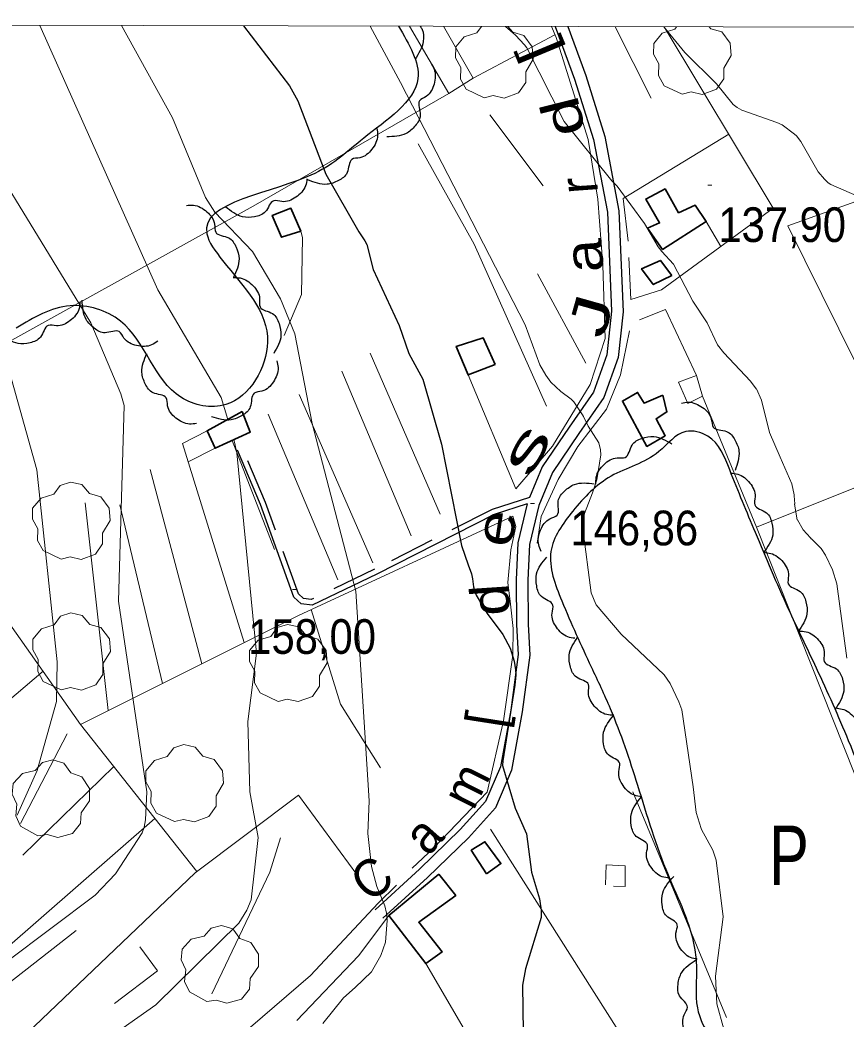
# Model space of a CAD drawing. Extents: x 480269 to 484877, y 4383588 to 4386804.
# Drawn here: x 481094.5 to 481302.9, y 4386204.5 to 4386456.6 of the extents above; entities that cross this region are included whole.
import ezdxf
from ezdxf.enums import TextEntityAlignment as Align

# ---------------------------------------------------------------- set-up
doc = ezdxf.new("R2010")
doc.units = 0
doc.header["$LTSCALE"] = 3.8
doc.linetypes.add('MEDIUM_DASHED', pattern=[4.5, 3, -1.5])
for name, color, linetype, lineweight in [('1', 7, 'Continuous', 13), ('27', 7, 'Continuous', 25), ('29', 7, 'Continuous', 13), ('38', 7, 'Continuous', 25), ('47', 7, 'Continuous', 35), ('51', 7, 'Continuous', 13), ('7', 7, 'Continuous', 13), ('8', 7, 'Continuous', 25), ('9', 7, 'Continuous', 13)]:
    doc.layers.add(name, color=color, linetype=linetype, lineweight=lineweight)
doc.layers.add('31', color=7, linetype='Continuous')
doc.layers.add('5', color=7, linetype='Continuous')

msp = doc.modelspace()

# ---------------------------------------------------------------- linework, layer by layer
at = {"layer": '1'}
msp.add_lwpolyline([(480529.1, 4386456.6), (484105.5, 4386448.1), (484100.5, 4384135.8), (480523.1, 4384144.4)], close=True, dxfattribs=at)
at = {"layer": '27'}
for points in [[(481189.94, 4386455.03), (481194.87, 4386441.86), (481181.19, 4386426.77), (481168.84, 4386417.89), (481141.6, 4386402.68), (481145.59, 4386395.9), (481156.94, 4386375.34), (481146.42, 4386359.57), (481135.09, 4386361.4), (481119.82, 4386380.64), (481107.1, 4386384.49), (481093.54, 4386378.88)], [(481195.45, 4386455.02), (481195.92, 4386454.22), (481196.23, 4386451.21), (481194.14, 4386446.72)], [(481198.09, 4386445.79), (481198.95, 4386444.23), (481198.95, 4386440.44), (481196.97, 4386437.32), (481195.27, 4386436.17), (481195.45, 4386432.62), (481194.19, 4386429.91), (481191.89, 4386427.95), (481187, 4386427.14)], [(481184.5, 4386429.24), (481184.69, 4386427.48), (481183.24, 4386423.97), (481180.22, 4386421.85), (481178.21, 4386421.43), (481177.01, 4386418.08), (481174.81, 4386416.07), (481171.94, 4386415.14), (481167.1, 4386416.26)], [(481166.88, 4386416.51), (481166.52, 4386414.77), (481164.07, 4386411.88), (481160.54, 4386410.78), (481158.5, 4386411), (481156.34, 4386408.18), (481153.63, 4386406.93), (481150.6, 4386406.93), (481146.35, 4386409.48)], [(481136.45, 4386409.79), (481138.23, 4386409.88), (481141.64, 4386408.21), (481143.56, 4386405.06), (481143.85, 4386403.03), (481147.12, 4386401.63), (481148.99, 4386399.3), (481149.74, 4386396.37), (481148.32, 4386391.62)], [(481148.27, 4386391.59), (481150.05, 4386391.51), (481153.29, 4386389.55), (481154.93, 4386386.24), (481155.04, 4386384.19), (481158.17, 4386382.51), (481159.83, 4386380.03), (481160.32, 4386377.04), (481158.48, 4386372.44)], [(481109.63, 4386385.54), (481109.38, 4386383.78), (481107.11, 4386380.74), (481103.66, 4386379.43), (481101.61, 4386379.52), (481099.63, 4386376.57), (481097, 4386375.16), (481093.98, 4386374.97), (481089.57, 4386377.25)], [(481129.21, 4386375.53), (481127.69, 4386374.61), (481123.9, 4386374.47), (481120.71, 4386376.33), (481119.49, 4386377.98), (481115.95, 4386377.67), (481113.2, 4386378.82), (481111.16, 4386381.05), (481110.16, 4386385.91)], [(481139.02, 4386354.79), (481137.25, 4386354.64), (481133.78, 4386356.17), (481131.73, 4386359.25), (481131.37, 4386361.27), (481128.05, 4386362.54), (481126.08, 4386364.79), (481125.23, 4386367.69), (481126.47, 4386372.49)], [(481159.28, 4386370.63), (481159.59, 4386368.88), (481158.39, 4386365.28), (481155.52, 4386362.96), (481153.54, 4386362.41), (481152.58, 4386358.98), (481150.52, 4386356.82), (481147.72, 4386355.7), (481142.82, 4386356.49)], [(481261.37, 4386359.92), (481263.12, 4386360.17), (481266.67, 4386358.83), (481268.89, 4386355.87), (481269.37, 4386353.88), (481272.75, 4386352.79), (481274.84, 4386350.66), (481275.86, 4386347.81), (481274.89, 4386342.95)], [(481320.35, 4386227.93), (481327.1, 4386209.36), (481329.69, 4386201.13), (481328.04, 4386199.61), (481317.88, 4386196.87), (481303.46, 4386193.44), (481292.76, 4386192), (481276.23, 4386194.04), (481268.74, 4386200.02), (481265.37, 4386207.33), (481265.15, 4386217.97), (481261.89, 4386231.76), (481257.97, 4386240.94), (481250.26, 4386263.55), (481243.38, 4386282.87), (481238.59, 4386293.38), (481231.16, 4386310.07), (481228.43, 4386322.5), (481233.94, 4386332.68), (481243.59, 4386341.49), (481255.64, 4386347.7), (481262.44, 4386352.76), (481268, 4386351.6), (481273.52, 4386343.13), (481280.01, 4386327.28), (481288.32, 4386308.12), (481295.44, 4386293.02), (481303.54, 4386274.74), (481320.35, 4386227.93)], [(481239.78, 4386339.47), (481239.86, 4386341.24), (481241.83, 4386344.48), (481245.14, 4386346.12), (481247.19, 4386346.22), (481248.88, 4386349.35), (481251.36, 4386351.01), (481254.35, 4386351.48), (481258.95, 4386349.64)], [(481273.82, 4386342.28), (481275.58, 4386342.03), (481278.62, 4386339.75), (481279.92, 4386336.3), (481279.83, 4386334.25), (481282.78, 4386332.27), (481284.19, 4386329.63), (481284.37, 4386326.62), (481282.09, 4386322.21)], [(481226, 4386322.51), (481225.35, 4386324.16), (481225.82, 4386327.92), (481228.18, 4386330.76), (481230.01, 4386331.69), (481230.28, 4386335.24), (481231.87, 4386337.76), (481234.4, 4386339.42), (481239.36, 4386339.61)], [(481234.44, 4386300.59), (481232.7, 4386300.94), (481229.8, 4386303.39), (481228.7, 4386306.91), (481228.91, 4386308.96), (481226.08, 4386311.11), (481224.83, 4386313.82), (481224.82, 4386316.84), (481227.35, 4386321.1)], [(481282.13, 4386322.23), (481283.89, 4386322.02), (481286.98, 4386319.81), (481288.36, 4386316.39), (481288.31, 4386314.34), (481291.3, 4386312.42), (481292.77, 4386309.82), (481293.02, 4386306.81), (481290.84, 4386302.35)], [(481244.27, 4386281.18), (481242.5, 4386281.35), (481239.37, 4386283.49), (481237.91, 4386286.88), (481237.91, 4386288.93), (481234.88, 4386290.78), (481233.35, 4386293.35), (481233.04, 4386296.36), (481235.12, 4386300.86)], [(481291.02, 4386302.43), (481292.78, 4386302.27), (481295.93, 4386300.15), (481297.4, 4386296.76), (481297.4, 4386294.71), (481300.44, 4386292.86), (481301.98, 4386290.3), (481302.3, 4386287.3), (481300.24, 4386282.79)], [(481300.6, 4386282.93), (481302.34, 4386282.6), (481305.27, 4386280.19), (481306.41, 4386276.68), (481306.22, 4386274.63), (481309.08, 4386272.51), (481310.37, 4386269.82), (481310.41, 4386266.8), (481307.92, 4386262.5)], [(481251.26, 4386260.62), (481249.52, 4386260.98), (481246.63, 4386263.44), (481245.55, 4386266.97), (481245.78, 4386269.01), (481242.96, 4386271.18), (481241.72, 4386273.9), (481241.73, 4386276.92), (481244.29, 4386281.17)], [(481258.26, 4386240.08), (481256.52, 4386240.44), (481253.64, 4386242.9), (481252.55, 4386246.43), (481252.77, 4386248.47), (481249.95, 4386250.63), (481248.71, 4386253.35), (481248.72, 4386256.37), (481251.27, 4386260.62)], [(481265.36, 4386219.62), (481263.64, 4386220.06), (481260.88, 4386222.67), (481259.97, 4386226.24), (481260.3, 4386228.27), (481257.59, 4386230.58), (481256.48, 4386233.35), (481256.64, 4386236.37), (481259.4, 4386240.49)], [(481265.56, 4386197.83), (481264.01, 4386198.7), (481262.01, 4386201.92), (481262.04, 4386205.61), (481262.88, 4386207.49), (481260.85, 4386210.41), (481260.49, 4386213.38), (481261.41, 4386216.25), (481265.14, 4386219.53)]]:
    msp.add_spline(points, degree=3, dxfattribs=at)
at = {"layer": '29'}
for points in [[(481211.58, 4386436.99), (481207.04, 4386439.11), (481205.63, 4386441.65), (481205.73, 4386444.63), (481204.36, 4386447.04), (481204.4, 4386449.79), (481206.56, 4386452.39), (481209.75, 4386453.39), (481210.95, 4386454.98)], [(481217.51, 4386454.96), (481218.78, 4386453.49), (481221.59, 4386452.67), (481223.72, 4386449.82), (481223.96, 4386446.69), (481222.08, 4386443.54), (481222.08, 4386440.86), (481220.26, 4386438.25), (481216.64, 4386436.91), (481213.87, 4386437.54), (481211.58, 4386436.99)], [(481261.54, 4386437.9), (481257, 4386440.02), (481255.59, 4386442.56), (481255.69, 4386445.54), (481254.32, 4386447.95), (481254.36, 4386450.7), (481256.52, 4386453.3), (481259.71, 4386454.3), (481260.13, 4386454.86)], [(481268.36, 4386454.84), (481268.74, 4386454.4), (481271.55, 4386453.58), (481273.68, 4386450.73), (481273.92, 4386447.6), (481272.04, 4386444.45), (481272.04, 4386441.77), (481270.22, 4386439.16), (481266.6, 4386437.82), (481263.83, 4386438.45), (481261.54, 4386437.9)]]:
    msp.add_lwpolyline(points, dxfattribs=at)
for points in [[(481104.82, 4386320.59), (481100.28, 4386322.71), (481098.87, 4386325.25), (481098.97, 4386328.23), (481097.6, 4386330.64), (481097.64, 4386333.39), (481099.8, 4386335.99), (481102.99, 4386336.99), (481104.64, 4386339.18), (481107.21, 4386340.01), (481110.07, 4386339.36), (481112.02, 4386337.09), (481114.83, 4386336.27), (481116.96, 4386333.42), (481117.2, 4386330.29), (481115.32, 4386327.14), (481115.32, 4386324.46), (481113.5, 4386321.85), (481109.88, 4386320.51), (481107.11, 4386321.14)], [(481104.9, 4386287.6), (481100.36, 4386289.72), (481098.95, 4386292.26), (481099.05, 4386295.24), (481097.68, 4386297.65), (481097.72, 4386300.4), (481099.88, 4386303), (481103.07, 4386304), (481104.72, 4386306.19), (481107.29, 4386307.02), (481110.15, 4386306.37), (481112.1, 4386304.1), (481114.91, 4386303.28), (481117.04, 4386300.43), (481117.28, 4386297.3), (481115.4, 4386294.15), (481115.4, 4386291.47), (481113.58, 4386288.86), (481109.96, 4386287.52), (481107.19, 4386288.15)], [(481159.57, 4386284.69), (481155.03, 4386286.81), (481153.62, 4386289.35), (481153.72, 4386292.33), (481152.35, 4386294.74), (481152.39, 4386297.49), (481154.55, 4386300.09), (481157.74, 4386301.09), (481159.39, 4386303.28), (481161.96, 4386304.11), (481164.82, 4386303.46), (481166.77, 4386301.19), (481169.58, 4386300.37), (481171.71, 4386297.52), (481171.95, 4386294.39), (481170.07, 4386291.24), (481170.07, 4386288.56), (481168.25, 4386285.95), (481164.63, 4386284.61), (481161.86, 4386285.24)], [(481133.44, 4386254.34), (481128.9, 4386256.46), (481127.49, 4386259), (481127.59, 4386261.98), (481126.22, 4386264.39), (481126.26, 4386267.14), (481128.42, 4386269.74), (481131.61, 4386270.74), (481133.26, 4386272.93), (481135.83, 4386273.76), (481138.69, 4386273.11), (481140.64, 4386270.84), (481143.45, 4386270.02), (481145.58, 4386267.17), (481145.82, 4386264.04), (481143.94, 4386260.89), (481143.94, 4386258.21), (481142.12, 4386255.6), (481138.5, 4386254.26), (481135.73, 4386254.89)], [(481099.01, 4386250.73), (481094.62, 4386253.16), (481093.4, 4386255.8), (481093.7, 4386258.76), (481092.5, 4386261.26), (481092.74, 4386264), (481095.07, 4386266.45), (481098.32, 4386267.22), (481100.12, 4386269.29), (481102.74, 4386269.94), (481105.55, 4386269.09), (481107.34, 4386266.69), (481110.09, 4386265.68), (481112.01, 4386262.69), (481112.03, 4386259.55), (481109.94, 4386256.53), (481109.75, 4386253.86), (481107.75, 4386251.38), (481104.05, 4386250.3), (481101.33, 4386251.12)], [(481141.62, 4386208.93), (481137.23, 4386211.36), (481136.01, 4386214), (481136.31, 4386216.96), (481135.11, 4386219.46), (481135.35, 4386222.2), (481137.68, 4386224.65), (481140.93, 4386225.42), (481142.73, 4386227.49), (481145.35, 4386228.14), (481148.16, 4386227.29), (481149.95, 4386224.89), (481152.7, 4386223.88), (481154.62, 4386220.89), (481154.64, 4386217.75), (481152.55, 4386214.73), (481152.36, 4386212.06), (481150.36, 4386209.58), (481146.66, 4386208.5), (481143.94, 4386209.32)]]:
    msp.add_lwpolyline(points, close=True, dxfattribs=at)
at = {"layer": '38'}
for points in [[(481232.66, 4386454.93), (481237.2, 4386442.58), (481242.06, 4386427.17), (481245.59, 4386408.46), (481246.68, 4386383), (481245.38, 4386371.44), (481241.77, 4386361.34), (481235.48, 4386352.24), (481228.8, 4386342.44), (481225.34, 4386334.13), (481223.02, 4386324.24), (481222.63, 4386315.26), (481222.66, 4386304.13), (481223.12, 4386296.37), (481221.18, 4386282.02), (481218.51, 4386267.33), (481214.44, 4386257.85), (481207.64, 4386250.28), (481197.31, 4386240.23), (481186.05, 4386229.95)], [(481229.52, 4386454.94), (481234.41, 4386441.63), (481239.19, 4386426.45), (481242.66, 4386408.13), (481243.73, 4386383.1), (481242.49, 4386372.11), (481239.13, 4386362.69), (481233.06, 4386353.9), (481226.2, 4386343.85), (481222.99, 4386336.15)], [(481222.41, 4386334.51), (481214.12, 4386331.83), (481184.54, 4386316.76), (481168.18, 4386308.96), (481165.41, 4386309.31), (481163.57, 4386310.99), (481155.12, 4386334.39), (481149.37, 4386348.03)], [(481222.41, 4386334.51), (481220.09, 4386324.65), (481219.68, 4386315.32), (481219.71, 4386304.03), (481220.17, 4386296.48), (481218.27, 4386282.48), (481215.68, 4386268.19), (481211.92, 4386259.45), (481205.51, 4386252.33), (481195.29, 4386242.38), (481184.06, 4386232.12)]]:
    msp.add_lwpolyline(points, dxfattribs=at)
at = {"layer": '38', "linetype": 'MEDIUM_DASHED'}
msp.add_lwpolyline([(481222.99, 4386336.15), (481213.59, 4386333.11), (481183.93, 4386318), (481167.95, 4386310.38), (481166.02, 4386310.63), (481164.75, 4386311.78), (481156.41, 4386334.9), (481150.65, 4386348.56)], dxfattribs=at)
at = {"layer": '47'}
for points in [[(481267.57, 4386405.76), (481264.81, 4386409.9), (481260.63, 4386407.95), (481257.22, 4386413.98), (481252.35, 4386411.43), (481255.82, 4386405.38), (481252.78, 4386404.05), (481256.59, 4386398.66)], [(481165.29, 4386403.33), (481160.46, 4386401.8), (481158.13, 4386407.27), (481162.82, 4386409.1)], [(481258.9, 4386392.13), (481256.06, 4386395.92), (481251.31, 4386393.83), (481254.22, 4386389.84)], [(481214.38, 4386369.69), (481211.3, 4386376.41), (481204.53, 4386374.24), (481207.51, 4386367.03)], [(481256.62, 4386361.96), (481251.91, 4386359.93), (481250.3, 4386362.64), (481246.45, 4386360.44), (481252.64, 4386349.02), (481257.27, 4386351.7), (481254.97, 4386355.97), (481257.7, 4386357.71)], [(481150.54, 4386357.85), (481152.58, 4386352.62), (481143.71, 4386348.56), (481141.67, 4386352.98)], [(481212.13, 4386241.2), (481215.8, 4386243.77), (481211.79, 4386249.26), (481208.33, 4386247.11)], [(481200.16, 4386241.1), (481204.4, 4386235.73), (481195.07, 4386228.97), (481200.98, 4386221.47), (481196.86, 4386218.52), (481187.53, 4386230.7)]]:
    msp.add_lwpolyline(points, close=True, dxfattribs=at)
at = {"layer": '47', "lineweight": 13}
msp.add_lwpolyline([(481265.12, 4386366.93), (481260.6, 4386365.19), (481262.99, 4386359.84), (481266.64, 4386361.71)], close=True, dxfattribs=at)
at = {"layer": '51'}
for p, q in [((481202.65, 4386438.02), (481192.74, 4386455.02)), ((481253.73, 4386436.89), (481244.59, 4386454.9)), ((481208.8, 4386441.88), (481202.65, 4386438.02)), ((481213.03, 4386432.68), (481226.48, 4386414.76)), ((481271.29, 4386399.47), (481267.57, 4386405.76)), ((481225.02, 4386392.53), (481237.25, 4386369.98)), ((481200.5, 4386331.93), (481182.85, 4386372.53)), ((481175.65, 4386368.02), (481193.13, 4386326.49)), ((481183.53, 4386319.66), (481164.94, 4386362.13)), ((481157.08, 4386357.17), (481174.65, 4386315.38)), ((481143.71, 4386348.56), (481136.93, 4386345.1)), ((481147.98, 4386350.52), (481158.66, 4386323.04)), ((481127.3, 4386343.19), (481140.35, 4386294.18)), ((481110.94, 4386334.75), (481116.75, 4386282.36)), ((481130.45, 4386289.22), (481119.63, 4386334.29)), ((481139.11, 4386241.77), (481109.74, 4386278.85)), ((481106.39, 4386276.53), (481094.56, 4386253.86)), ((481095.2, 4386245.88), (481118.14, 4386268.26)), ((481272.75, 4386204.93), (481249.08, 4386261.89)), ((481128.51, 4386255.16), (481090.48, 4386221.87)), ((481108.66, 4386226.86), (481081.61, 4386205.79)), ((481212.47, 4386191.97), (481196.86, 4386218.52))]:
    msp.add_line(p, q, dxfattribs=at)
for points in [[(481201.36, 4386455), (481208.8, 4386441.88), (481229.45, 4386452.83)], [(481207.51, 4386367.03), (481219.55, 4386338.28), (481228.85, 4386349.11), (481238.29, 4386364.66), (481242.12, 4386376.26), (481241.48, 4386394.74), (481240.25, 4386411.37), (481237.85, 4386426.45), (481229.72, 4386452.15), (481228.57, 4386454.94)], [(481248.11, 4386396.7), (481248.61, 4386386.07), (481256.32, 4386388.51), (481284.52, 4386409.15), (481257.01, 4386454.87)], [(481426.51, 4386454.47), (481382.4, 4386438.35), (481288.18, 4386404.68), (481318.33, 4386343.83), (481280.3, 4386328.64), (481266.64, 4386361.71)], [(481053.37, 4386354.18), (481153.3, 4386409.6), (481202.65, 4386438.02)], [(481273.3, 4386427.81), (481246.61, 4386411.54), (481247.93, 4386400.79)], [(481227.27, 4386359.13), (481209.04, 4386400.04), (481194.9, 4386425.38)], [(481161.09, 4386377.02), (481165.5, 4386387.37), (481165.74, 4386401.68), (481165.29, 4386403.33)], [(481265.12, 4386366.93), (481257.31, 4386383.52), (481250.74, 4386380.93)], [(481248.23, 4386378.14), (481245.97, 4386367.1), (481242.42, 4386358.39), (481235.24, 4386349), (481230.27, 4386340.64), (481225.99, 4386331.36), (481224.98, 4386324.62)], [(481151.01, 4386299.51), (481135.48, 4386349.77), (481141.67, 4386352.98)], [(481080.84, 4386319.8), (481109.74, 4386278.85), (481164.74, 4386306.39), (481218.85, 4386331.4), (481219.55, 4386328.77), (481218.29, 4386322.88), (481217.56, 4386314.64), (481218.25, 4386309.25), (481218.87, 4386303.11), (481218.83, 4386296.33), (481216.44, 4386279.79), (481212.31, 4386261.77), (481198.85, 4386247.77), (481193.39, 4386242.61)], [(481280.3, 4386328.64), (481316.03, 4386238.76), (481353.68, 4386144.85), (481396.75, 4386152.18), (481450.8, 4386166.74), (481535.15, 4386190.59)], [(481185.42, 4386267.94), (481175.34, 4386284.02), (481167.92, 4386307.86)], [(481054.37, 4386247.6), (481073.02, 4386269.07), (481100.28, 4386292.27)], [(481189.43, 4386238.35), (481184.8, 4386233.8), (481167.77, 4386215.52), (481149.6, 4386199.89), (481132.43, 4386187.68), (481111.54, 4386176.08), (481088.62, 4386168.47), (481055.25, 4386162.19), (481090.79, 4386195.75), (481138.64, 4386241.42), (481164.71, 4386260.99), (481179.45, 4386241.02)], [(481213.22, 4386252.41), (481265.46, 4386170.05), (481265.32, 4386167.49), (481264.01, 4386164.98), (481240.52, 4386149.28)], [(481142.87, 4386210.92), (481157.54, 4386241.61), (481160.2, 4386250.26)], [(481242.22, 4386238.42), (481242.32, 4386243.4), (481247.13, 4386243.18), (481247.12, 4386237.97), (481244.23, 4386238.06)], [(481187.53, 4386230.7), (481179.87, 4386220.51), (481164.3, 4386204.15)], [(481124.67, 4386222.74), (481129.13, 4386216.69), (481118.3, 4386208.48)]]:
    msp.add_lwpolyline(points, dxfattribs=at)
at = {"layer": '7'}
for p, q in [((481268, 4386414.95), (481269, 4386414.95)), ((481223.25, 4386334.64), (481224.25, 4386334.64)), ((481163.19, 4386312.88), (481164.19, 4386312.88))]:
    msp.add_line(p, q, dxfattribs=at)
at = {"layer": '8'}
msp.add_lwpolyline([(481150.83, 4386455.12), (481162.43, 4386439.95), (481164.53, 4386436.23), (481171.62, 4386417.69), (481179.93, 4386403.13), (481181.48, 4386400.89), (481181.98, 4386399.95), (481183.59, 4386393.62), (481190.15, 4386379.52), (481192.57, 4386372.47), (481196.14, 4386365.95), (481200.81, 4386349.6), (481205.9, 4386324), (481207.52, 4386319.12), (481208.38, 4386316.88), (481208.67, 4386315.61), (481208.91, 4386313.6), (481209.12, 4386312.65), (481209.54, 4386311.46), (481212.34, 4386306.82), (481216.3, 4386301.54), (481218.13, 4386298.08), (481219.14, 4386294.82), (481219.49, 4386292.66), (481219.55, 4386291.29), (481219.33, 4386288.8), (481216.26, 4386269.69), (481216.21, 4386268.51), (481219.43, 4386257.73), (481222.23, 4386251.23), (481223.5, 4386241.62), (481225.54, 4386234.85), (481225.98, 4386231.97), (481225.97, 4386230.19), (481221.97, 4386217.19), (481221.27, 4386213.07), (481221.54, 4386195.32)], dxfattribs=at)
at = {"layer": '9'}
for points in [[(481025.25, 4386167.22), (481026.34, 4386167.59), (481030.34, 4386169.8), (481062.15, 4386200.1), (481091.1, 4386219.01), (481113.42, 4386235.76), (481118.59, 4386241.2), (481125.31, 4386251.51), (481125.84, 4386252.95), (481126.17, 4386254.79), (481126.47, 4386261.82), (481119.29, 4386309.93), (481120.76, 4386359.37), (481119.92, 4386362.24), (481112.34, 4386380.2), (481073.31, 4386443.98), (481068.88, 4386455.32)], [(481146.88, 4386355.84), (481145.19, 4386361.35), (481129.27, 4386388.55), (481099.44, 4386455.24)], [(481170.84, 4386203.4), (481176.07, 4386209.91), (481179.04, 4386212.48), (481183.12, 4386216.42), (481185.51, 4386220.53), (481186.7, 4386223.96), (481187.08, 4386229.42), (481186.93, 4386231.26), (481186.5, 4386233.1), (481184.5, 4386238.01), (481183.13, 4386243.02), (481182.21, 4386251.32), (481182.58, 4386259.63), (481179.23, 4386312.48), (481168.15, 4386354.81), (481163.84, 4386377.42), (481160.2, 4386386.24), (481153.12, 4386398.21), (481143.63, 4386408.08), (481141.27, 4386411.77), (481132.97, 4386431.89), (481120.12, 4386455.2)], [(481272.08, 4386201.94), (481270.32, 4386208.4), (481269.91, 4386215.32), (481271.85, 4386230.35), (481270.14, 4386244.58), (481269.27, 4386247.1), (481266.43, 4386252.36), (481266.33, 4386252.57), (481265.06, 4386256.61), (481264.31, 4386263.11), (481261.45, 4386282.53), (481260.7, 4386284.58), (481258.49, 4386289.23), (481256.96, 4386291.38), (481256.89, 4386291.46), (481246.16, 4386301.67), (481239.85, 4386309), (481239.75, 4386309.19), (481238.58, 4386312.08), (481236.44, 4386328.21), (481236.61, 4386330.92), (481236.88, 4386332.07), (481238.95, 4386337.32), (481240.04, 4386340.61), (481241.05, 4386346.9), (481240.96, 4386348.13), (481240.52, 4386349.94), (481237.79, 4386354.14), (481236.63, 4386356.59), (481236.43, 4386356.97), (481234.24, 4386360.22), (481233.54, 4386360.91), (481230.91, 4386362.87), (481228.44, 4386365.2), (481228.43, 4386365.21), (481228.41, 4386365.22), (481227.11, 4386366.99), (481225.63, 4386369.61), (481221.89, 4386379.67), (481190.48, 4386440.86), (481182.8, 4386455.05)], [(481216.98, 4386454.97), (481219.48, 4386452.78), (481221.77, 4386450.3), (481222.32, 4386449.55), (481231.8, 4386430.95), (481243.77, 4386416.05), (481245.16, 4386414.7), (481252.05, 4386405.29), (481255.49, 4386399.34), (481256.38, 4386398.22), (481259.38, 4386394.96), (481264.26, 4386385.68), (481267.87, 4386380.21), (481270.41, 4386374.65), (481272.05, 4386372.6), (481278.76, 4386365.47), (481280.24, 4386363.55), (481280.25, 4386363.53), (481281.51, 4386360.65), (481283.53, 4386352.49), (481286.26, 4386346.28), (481289.19, 4386339.58), (481289.82, 4386336.76), (481289.83, 4386336.56), (481289.94, 4386334.52), (481289.91, 4386334.44), (481290.59, 4386330.46), (481290.6, 4386330.46), (481292.07, 4386328), (481293.88, 4386325.92), (481294.09, 4386325.73), (481294.18, 4386325.7), (481296.57, 4386323.27), (481297.73, 4386321.55), (481299.47, 4386317.83), (481300.59, 4386314.36), (481303.05, 4386295.56)], [(481305.6, 4386412.22), (481299.03, 4386415.12), (481298.39, 4386415.55), (481297.41, 4386416.42), (481295.85, 4386418.25), (481291.48, 4386425.95), (481290.34, 4386427.39), (481289.9, 4386427.8), (481286.74, 4386430.15), (481285.4, 4386430.76), (481276.58, 4386433.81), (481275.38, 4386434.5), (481274.37, 4386435.29), (481270.21, 4386440.47), (481262.22, 4386448.38), (481256.92, 4386454.87)], [(481093.73, 4386255.97), (481098.82, 4386267.25), (481103.68, 4386284.63), (481103.82, 4386294.68), (481098.71, 4386343.06), (481089.73, 4386375.3)], [(481082.1, 4386175.35), (481128.74, 4386208.16), (481149.72, 4386228.72), (481151.72, 4386232), (481152.77, 4386234.57), (481154.53, 4386250.37), (481152.42, 4386261.86), (481151.97, 4386279.59), (481154.14, 4386296.85), (481149.19, 4386347.39), (481148.62, 4386350.12), (481148.44, 4386350.72)]]:
    msp.add_lwpolyline(points, dxfattribs=at)

# ---------------------------------------------------------------- texts
at = {"layer": '31', "width": 0.75}
msp.add_text('P', height=15, dxfattribs=at).set_placement((481288.48, 4386238.33), align=Align.CENTER)
at = {"layer": '5'}
for s, rotation, width, p in [('[', 112.617, 1.3, (481229.04, 4386450.39)), ('d', 104.028, 1.4, (481236.06, 4386433.25)), ('a', 94.178, 1.2, (481241.43, 4386397.39)), ('J', 74.266, 1.6, (481243.05, 4386380.73)), ('s', 60.466, 1.95, (481226.05, 4386346.01)), ('e', 81.585, 1.3, (481219.11, 4386327.77)), ('d', 93.801, 1.15, (481217.84, 4386310.62)), ('m', 63.435, 0.95, (481211.14, 4386261.46)), ('a', 48.158, 0.95, (481199.69, 4386247.86)), ('C', 39.399, 0.95, (481186.21, 4386236.4))]:
    msp.add_text(s, height=9.49, rotation=rotation, dxfattribs=dict(at, width=width)).set_placement(p, align=Align.CENTER)
for s, rotation, p in [('r', 94.057, (481240.15, 4386415.15)), ('[', 81.122, (481216.47, 4386279.47))]:
    msp.add_text(s, height=9.49, rotation=rotation, dxfattribs=at).set_placement(p, align=Align.CENTER)
at = {"layer": '7', "width": 0.9}
for s, p in [('137,90', (481270.66, 4386400.58)), ('146,86', (481233.35, 4386324.05)), ('158,00', (481152.07, 4386296.67))]:
    msp.add_text(s, height=8.75, dxfattribs=at).set_placement(p)

doc.saveas('drawing.dxf')
